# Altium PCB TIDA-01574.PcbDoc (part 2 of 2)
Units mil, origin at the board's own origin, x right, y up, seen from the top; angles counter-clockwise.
Board outline 4950 x 3450 mil, 2 copper layers (Top Layer, Bottom Layer), stack 62 mil thick; 82 components, 33 nets, 179 pads, 119 vias.
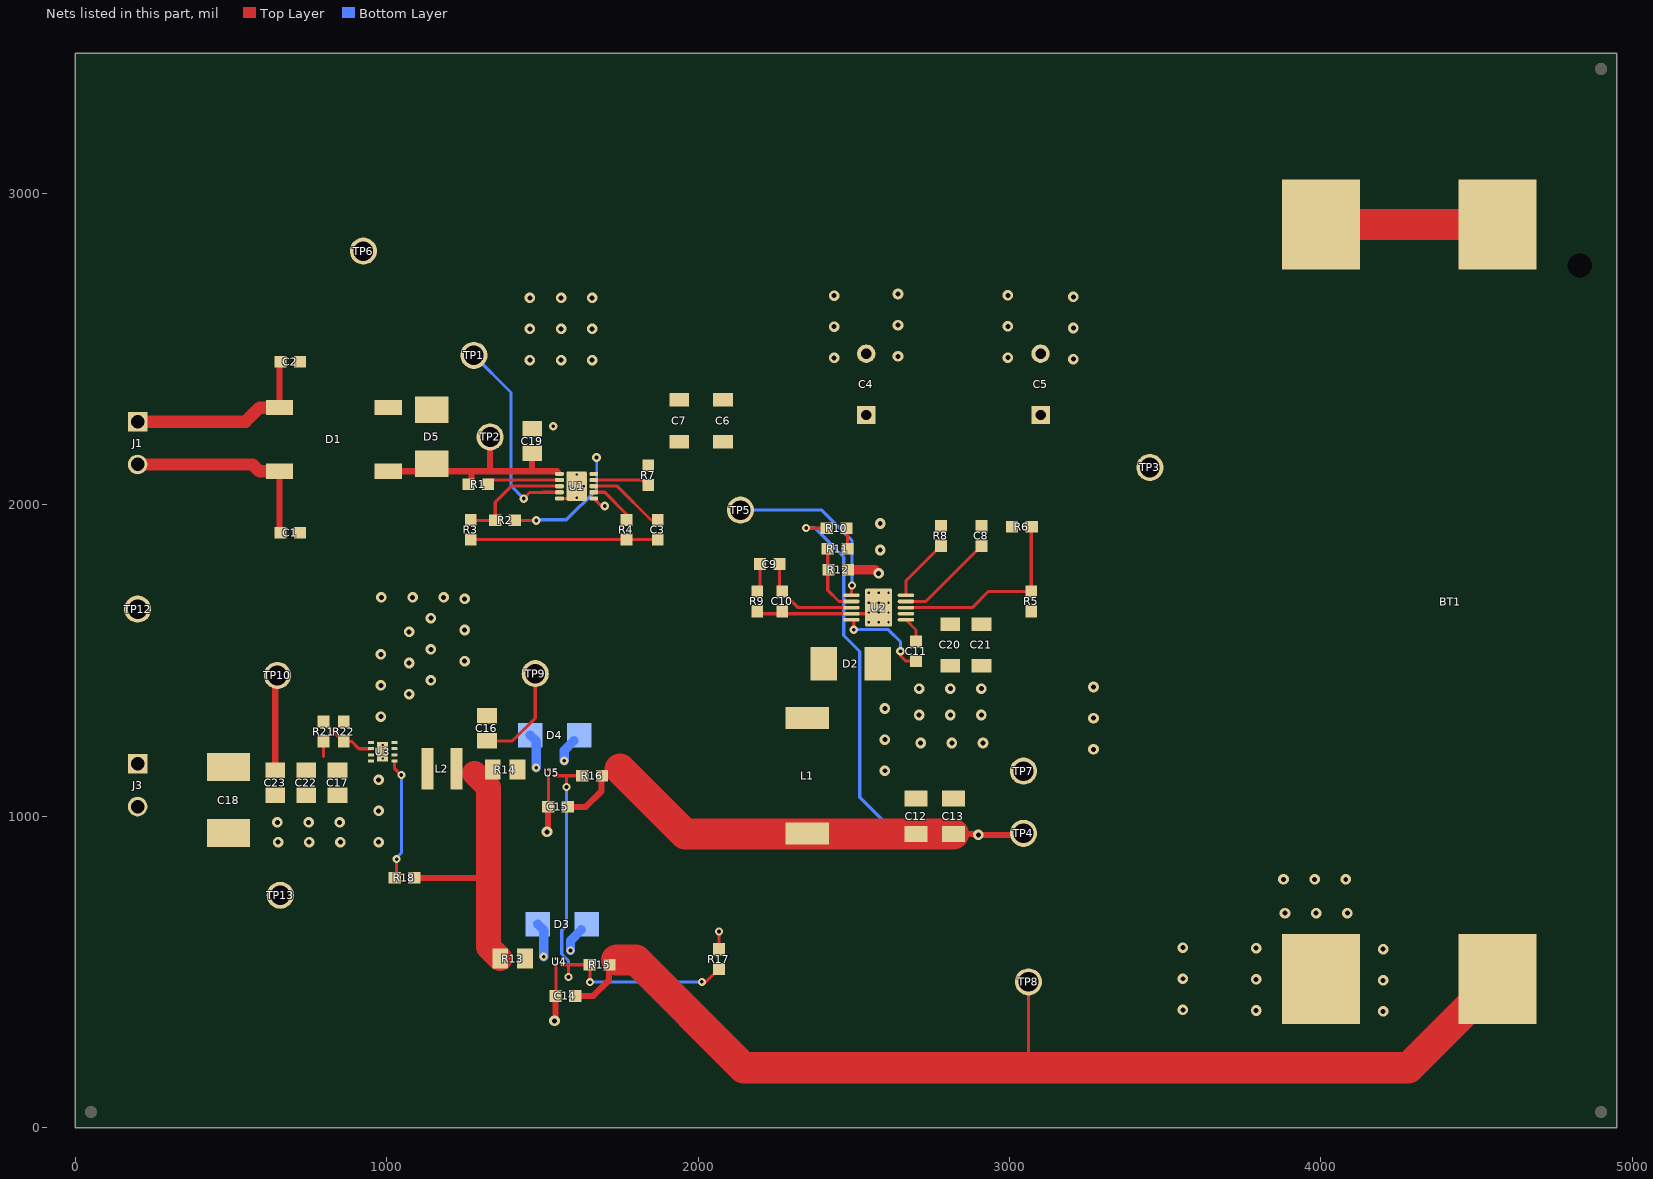
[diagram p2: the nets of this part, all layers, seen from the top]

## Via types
v1: diameter 34, hole 16, Top Layer to Bottom Layer, 81 vias
v2: diameter 26, hole 12, Top Layer to Bottom Layer, 13 vias
v3: diameter 19.68, hole 7.87, Top Layer to Bottom Layer, 12 vias
v4: diameter 28, hole 12, Top Layer to Bottom Layer, 7 vias
v5: diameter 19.68, hole 7.87, Top Layer to Bottom Layer, tented both sides, 6 vias

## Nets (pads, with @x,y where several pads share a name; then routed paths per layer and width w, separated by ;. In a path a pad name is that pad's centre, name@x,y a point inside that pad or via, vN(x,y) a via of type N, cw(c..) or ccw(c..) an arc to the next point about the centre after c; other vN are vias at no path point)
3p3V: C12.1 C13.1 C15.1 D4.2 L1.2 R10.2 R16.1 TP4.1 U5.A2 | length 3111.6
  Top Layer w10: 1958.09,942.91 1971.76,929.24 ; v2(2347,1926) 2348,1925 R10.2@2413.5,1925
  Top Layer w20: C15.1@1581.34,1029.84 1639.84,1029.84 1689.84,1079.84 R16.1@1689.84,1129.84 ; C13.1@2820,942.91 2897.09,942.91 v1(2900,940) 3040,940 TP4.1@3045,945
  Top Layer w100: 1749,1152 1958.09,942.91 C12.1@2700,942.91 C13.1@2820,942.91
  Bottom Layer w10: v2(2347,1926) 2374.27,1926 2467.65,1832.62 2467.65,1580.35 2519,1529 2519,1061 2640,940 v1(2900,940)
  Bottom Layer w30: v2(1570,1178) 1570,1211.26 D4.2@1600.87,1242.13
GND: BT1.3 C1.2 C2.2 C4.2 C5.2 C6.2 C7.2 C8.2 C10.2 C12.2 C13.2 C14.2 C15.2 C16.2 C17.2 C18.2 C19.2 C20.2 C21.2 C22.2 C23.2 D1.2 D2.2 D5.2 J3.2 R6.1 R8.1 R9.1 R12.1 R17.1 R22.1 TP6.1 TP7.1 TP12.1 TP13.1 U1.6 U2.9 U2.11@2580,1670 U3.1 U3.9@987,1207 U4.B1 U5.B1 | length 937.9
  Top Layer w10: C15.2@1518.35,1029.84 1520,1031.5 U5.B1@1520,1130 ; C14.2@1542.35,422.84 1544,424.5 U4.B1@1544,523 ; U1.6@1665.12,2020.63 v4@1689.75,1996 ; R17.1@2067,572.5 R17.1@2067,575.5 ; v2(2067,630) R17.1@2067,575.5 ; R17.1@2070,572.5 R17.1@2067,575.5 ; R9.1@2190,1658.5 2198.19,1650.31 U2.9@2492.4,1650.31 U2.11@2560.31,1650.31
  Top Layer w20: v1(1514.84,949.84) 1518.35,953.35 C15.2@1518.35,1029.84 ; v1(1538.84,342.84) 1542.35,346.35 C14.2@1542.35,422.84
  Top Layer w30: R12.1@2481.5,1791 2569,1791 v1(2580,1780)
  other v1: 4200,373 3792,376 3557,378 4200,473 3792,476 3557,478 4200,573 3792,576 3557,578 3885,689 3985,689 4085,689 3880,797 3980,797 4080,797 651,917 751,917 851,917 974,917 649,980 749,980 849,980 974,1017 974,1117 2600,1146 3270,1215 2715,1235 2815,1235 2915,1235 2600,1246 3270,1315 981,1320 2710,1325 2810,1325 2910,1325 2600,1346 1072,1392 2710,1410 2810,1410 2910,1410 3270,1415 981,1420 1142,1436 1072,1492 1250,1498 981,1520 1142,1536 1072,1592 1250,1598 1142,1636 1250,1698 983,1703 1083,1703 1183,1703 2585,1855 2585,1940 1460,2465 1560,2465 1660,2465 3205,2468 2437,2472 2995,2473 2642,2477 1460,2565 1560,2565 1660,2565 3205,2568 2437,2572 2995,2573 2642,2577 1460,2665 1560,2665 1660,2665 3205,2668 2437,2672 2995,2673 2642,2677
  other v3: 987,1185.35 987,1228.65 2548.5,1654.25 2580,1654.25 2611.5,1654.25 2548.5,1685.75 2580,1685.75 2611.5,1685.75
  other v4: 1700,1996 1535,2252
  other v5: 2548.5,1622.76 2580,1622.76 2611.5,1622.76 2548.5,1717.24 2580,1717.24 2611.5,1717.24
NetBT1_1: BT1.1 C14.1 D3.2 R15.1 TP8.1 U4.A2 | length 3597.5
  Top Layer w10: 3061,221 TP8.1@3061,468
  Top Layer w20: C14.1@1605.34,422.84 1663.84,422.84 1713.84,472.84 R15.1@1713.84,522.84
  Top Layer w100: 1738.82,537.84 1800.16,537.84 2146,192 4281.88,192 BT1.1@4567.86,477.98
  Bottom Layer w30: v2(1590,569) 1590,600.26 1594,604.26 D3.2@1624.87,635.13
NetBT1_2: BT1.2 BT1.4 | length 567.7
  Top Layer w100: BT1.4@4000.14,2900.02 BT1.2@4567.86,2900.02
NetC1_1: C1.1 D1.4 J1.2 | length 659.2
  Top Layer w20: C1.1@655.5,1913 D1.4@655.5,2107.64
  Top Layer w40: J1.2@200,2129.6 569.54,2129.6 591.5,2107.64 D1.4@655.5,2107.64
NetC2_1: C2.1 D1.3 J1.1 | length 618.8
  Top Layer w20: D1.3@655.5,2312.36 C2.1@655.5,2457
  Top Layer w40: J1.1@200,2267.39 546.53,2267.39 591.5,2312.36 D1.3@655.5,2312.36
NetC3_1: C3.1 U1.8 | length 249.8
  Top Layer w10: U1.8@1665.12,2060 1740,2060 1848.5,1951.5 C3.1@1870,1951.5
NetC3_2: C3.2 R3.1 R4.1 U1.5 U1.11@1610,2060 | length 683.1
  Top Layer w10: R3.1@1270,1888.5 R4.1@1770,1888.5 C3.2@1870,1888.5 ; U1.5@1554.88,2020.63 1590.63,2020.63 1610,2040 U1.11@1610,2060
  other v3: 1610,2022.6 1587.36,2060 1632.64,2060 1610,2097.4
NetC4_1: C4.1 C5.1 C6.1 C7.1 C20.1 C21.1 R2.2 R5.2 R7.2 TP3.1 U1.10 U2.2 | length 406.5
  Top Layer w10: R2.2@1411.5,1950 v4(1480,1950)
  Bottom Layer w8: 1674,2049 v4(1674,2152)
  Bottom Layer w10: v4(1480,1950) 1482,1952 1577,1952 1674,2049
NetC8_1: C8.1 U2.4 | length 316.5
  Top Layer w10: U2.4@2667.6,1689.68 2731.18,1689.68 C8.1@2910,1868.5
NetC9_1: C9.1 C10.1 U2.8 | length 335.8
  Top Layer w10: C9.1@2261.5,1810 2261.5,1730 C10.1@2270,1721.5 2321.5,1670 U2.8@2492.4,1670
NetC9_2: C9.2 R9.2 | length 80
  Top Layer w10: R9.2@2198.5,1730 C9.2@2198.5,1810
NetC11_1: C11.1 D2.1 L1.1 U2.10 | length 291.9
  Top Layer w10: v4(2500,1599.13) 2500,1623.03 ; v4(2650,1530) 2650,1515 2666.5,1498.5 C11.1@2700,1498.5
  Bottom Layer w10: v4(2500,1599.13) 2610.87,1599.13 2650,1560 v4(2650,1530)
NetC11_2: C11.2 U2.1 | length 82.6
  Top Layer w10: U2.1@2667.6,1630.63 2700,1598.23 C11.2@2700,1561.5
NetC16_1: C16.1 L2.1 R13.2 R14.2 R18.1 TP9.1 U3.8 | length 1195.7
  Top Layer w10: C16.1@1322,1242 1404,1242 1477,1315 TP9.1@1477,1458
  Top Layer w20: R18.1@1088.5,802 1327,802
  Top Layer w80: 1282,1138 1327,1093 1327,802 1327,580 R13.2@1364,543
NetC17_1: C17.1 C18.1 C22.1 C23.1 J3.1 R21.2 TP10.1 U3.3 U3.4 | length 356.4
  Top Layer w10: 797,1192 R21.2@797,1240.5
  Top Layer w20: C23.1@642,1147 642,1445 TP10.1@649,1452
NetC19_1: C19.1 D1.1 D5.1 R1.2 TP2.1 U1.1 | length 742.4
  Top Layer w20: D1.1@1004.5,2107.64 1272,2107.64 ; R1.2@1272,2075.5 1272,2107.64 ; 1332,2110.64 TP2.1@1332,2218 ; 1467,2108.64 C19.1@1467,2165 ; U1.1@1549.96,2105 1547.32,2107.64 1272,2107.64
NetD3_1: D3.1 R13.1 U4.A1 | length 112.2
  Top Layer w10: R13.1@1444,543 R13.1@1444.31,542.68
  Bottom Layer w30: D3.1@1485.26,653 1504,634.26 v2(1504,549)
NetD4_1: D4.1 R14.1 U5.A1 | length 112.2
  Top Layer w10: R14.1@1420,1150 R14.1@1420.31,1149.68
  Bottom Layer w30: D4.1@1461.26,1260 1480,1241.26 v2(1480,1156)
NetL2_2: L2.2 U3.6 U3.7
NetR1_1: R1.1 U1.2 | length 235.2
  Top Layer w10: R1.1@1319.69,2079.69 U1.2@1554.88,2079.69
NetR2_1: R2.1 R3.2 U1.3 | length 363.2
  Top Layer w10: R3.2@1271.5,1950 R2.1@1348.5,1950 1348.5,2008.5 1400,2060 U1.3@1554.88,2060
NetR4_2: R4.2 U1.7 | length 134
  Top Layer w10: U1.7@1665.12,2040.31 1699.69,2040.31 R4.2@1770,1970
NetR5_1: R5.1 R6.2 U2.3 | length 630.7
  Top Layer w10: U2.3@2667.6,1670 2880,1670 2931.5,1721.5 R5.1@3070,1721.5 R6.2@3070,1928.5
NetR7_1: R7.1 U1.9 | length 181.5
  Top Layer w10: U1.9@1665.12,2079.68 1818.82,2079.68 R7.1@1838.5,2060
NetR8_2: R8.2 U2.5 | length 205.7
  Top Layer w10: U2.5@2667.6,1709.37 2667.6,1756.1 R8.2@2780,1868.5
NetR10_1: R10.1 R11.2 | length 67.2
  Top Layer w10: R10.1@2476.5,1925 2479.5,1922 R11.2@2479.5,1859
NetR11_1: R11.1 R12.2 U2.7 | length 224.2
  Top Layer w10: R11.1@2416.5,1859 2416.5,1725.5 2452.32,1689.68 U2.7@2492.4,1689.68
NetR15_2: R15.2 R16.2 R17.2 U4.B2 U5.B2 | length 1359.4
  Top Layer w10: U5.B2@1539.68,1130 1579.68,1130 1579.84,1129.84 R16.2@1628.35,1129.84 ; U4.B2@1563.68,523 1603.68,523 1603.84,522.84 R15.2@1652.35,522.84 1652.35,473.35 1653,472.69 v2(1653,467) ; v2(1577,1094) 1577,1127 ; v2(1584,484) 1584,520 ; v2(2012,468) 2025.5,468 R17.2@2067,509.5
  Bottom Layer w10: v2(1577,1094) 1577,648.55 1562.13,633.68 1562.13,557.45 1584,535.58 v2(1584,484) ; v2(1653,467) 2011,467 v2(2012,468)
NetR18_2: R18.2 U3.5 | length 393.7
  Top Layer w10: U3.5@1024.4,1177.47 1024.4,1154.6 v2(1047,1132) ; R18.2@1025.5,802 1027,803.5 1032,808.5 v2(1032,862)
  Bottom Layer w10: v2(1032,862) 1032,867 1047,882 v2(1047,1132)
NetR21_1: R21.1 R22.2 U3.2 | length 188.5
  Top Layer w10: R21.1@797,1303.5 859.99,1240.5 R22.2@862,1240.5 886.76,1240.5 910.42,1216.84 U3.2@949.6,1216.84
NetTP1_1: TP1.1 U1.4 | length 649.6
  Top Layer w10: v4(1440,2020) 1460,2040 1500,2040 1500.32,2040.32 U1.4@1554.88,2040.32
  Bottom Layer w10: TP1.1@1280,2480 1399,2361 1399,2061 v4(1440,2020)
NetTP5_1: TP5.1 U2.6 | length 576.1
  Top Layer w10: U2.6@2492.4,1709.37 2492.4,1740.4 2493,1741 v2(2494,1741)
  Bottom Layer w10: TP5.1@2136,1983 2397,1983 2494,1886 v2(2494,1741)
pads on no net: BT1.MH1 FID1.1 FID2.1 FID3.1 H1.0 H2.0 H3.0 H4.0 U1.11@1600.16,1999.76 U1.11@1600.16,2120.24 U1.11@1610,2035.2 U1.11@1610,2084.8 U1.11@1619.84,1999.76 U1.11@1619.84,2120.24 U2.11@2580,1670 U3.9@987,1189.28 U3.9@987,1224.72

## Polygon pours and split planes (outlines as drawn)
GND on Top Layer "TOP_LAYER_GND_P000" (solid, remove dead copper, pour order 0): 700,1880 700,3450 4950,3450 4950,2440 2340,2440 2200,2300 1815,2300 1550,2300 1550,2220 1370.26,2220 1370.26,2280 950,2280 950,1880
GND on Bottom Layer "BOTTOM_LAYER_GND_P002" (solid, remove dead copper, pour order 2): 0,0 4950,0 4950,3450 0,3450

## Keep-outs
Keep-Out Layer:
  text ".Layer_Name" at 577,-858.49 h60

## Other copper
Top Layer:
  rectangle net NetC19_1: 1535,2095 1565,2120
  rectangle net NetC3_2: 1576.15,1855 1645,2275
  rectangle net GND: 2535,1395 2625,1975
  rectangle net GND: 2535,1900 3030,1975
  region net 3p3V: 1535,1145 1597,1145 1597,1157 1666,1157 1666,1111 1772,1111 1772,1194 1535,1194
  region net NetD3_1: 1550,538 1540,538 1510,508 1419,508 1419,575 1550,575
  region net NetBT1_1: 1559,538 1621,538 1621,550 1690,550 1690,504 1796,504 1796,587 1559,587
  region net NetD4_1: 1526,1145 1516,1145 1486,1115 1395,1115 1395,1182 1526,1182
  region net GND: 902,1098 128,1098 128,870 1005,870 1005,1287 1367,1287 1367,1799 844,1799 844,1285 888.3,1285 942.3,1231 969,1231 969,1165
  region net NetC16_1: 1017,1232 1197,1232 1197,1077 1367,1077 1367,1267 1017,1267
  region net NetL2_2: 1017,1222 1157,1222 1157,1077 1107,1077 1077.92,1106.08 1077.92,1161.08 1047,1192 1017,1192
  region net NetC17_1: 960,1202 128,1202 128,1122 911,1122 960,1171
  region net NetC4_1: 1655,2095 2200,2095 2300,1995 3570,1995 3570,2325 2300,2325 2200,2225 1655,2225
  region net NetC4_1: 2670,1655 2935,1655 2960,1680 3050,1680 3160,1680 3180,1700 3180,2000 3165,2015 3165,2325 3330,2325 3330,2005 3330,1550 2800,1550 2704.26,1645.74 2675.54,1645.74
  region net GND: 2535,1510 2630,1510 2630,1465 2740,1465 2780,1505 4252,1505 4252,1025 4252,305 3385,305 3385,1025 2535,1025
  region net NetC11_1: 2515,1635 2445,1635 2355,1550 2355,1435 2270,1350 2270,1275 2450,1275 2450,1520 2475,1545 2515,1585
  text ".Layer_Name" at 577,-858.49 h60
Bottom Layer:
  text ".Layer_Name" at 577,-858.49 h60

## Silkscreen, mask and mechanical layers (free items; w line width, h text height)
Top Overlay:
  region: 2646,196 2346,196 2346,96 2646,96
  text "'.PRJ_Number'.PCB_Rev-" at 1595,114 h108.27
  text ".Layer_Name" at 577,-858.49 h60
Bottom Overlay:
  text ".Layer_Name" at 577,-858.49 h60
Top Paste:
  text ".Layer_Name" at 577,-858.49 h60
Bottom Paste:
  text ".Layer_Name" at 577,-858.49 h60
Top Solder:
  text ".Layer_Name" at 577,-858.49 h60
  text ".Layer_Name" at 577,-858.49 h60
Bottom Solder:
  text ".Layer_Name" at 577,-858.49 h60
Drill Guide:
  text ".Layer_Name" at 577,-858.49 h60
M1 Board Outline:
  the board outline again, w10
  text ".Layer_Name" at 577,-858.49 h60
M2 Board Dimensions:
  rectangle: 0,-275 125,-150
  rectangle: 125,-400 500,-275
  lines w7: 0,-275 1000,-275 ; 125,-400 125,-150 ; 250,-400 250,-150 ; 500,-400 500,-150 ; 750,-400 750,-150 ; 0,-400 1000,-400 1000,-150 0,-150 0,-400
  text ".Layer_Name" at 577,-858.49 h60
M3 3D STEP Top:
  text ".Layer_Name" at 577,-858.49 h60
M4 3D STEP Bottom:
  text ".Layer_Name" at 577,-858.49 h60
M5 Assembly Top:
  lines w10: -292,-930.17 6308,-930.17 ; -292,-726.83 6310,-726.83 ; -292,-523.5 -292,-1133.5 3713,-1133.5 6310,-1133.5 6310,-523.5 -291.5,-523.5 -291.5,-1133.5 1284,-1133.5 ; 2173,-1133.5 2173,-523.5 ; 3440,-726.83 3440,-523.5 ; 4280,-726.83 4280,-523.5 ; 4902,-1140 4902,-937.17
  text "COMPONENTS MARKED 'DNP' SHOULD NOT BE POPULATED." at 1153.5,-318.5 h60
  text "ASSEMBLY VARIANT:" at 1153,-434 h60
  text ".VariantName" at 2189,-434 h60
  text "PCB VIEWED FROM TOP SIDE" at -228.5,-655.67 h60
  text "BOARD #:" at 2248,-655.67 h60
  text ".PRJ_Number" at 2793.5,-655.67 h60
  text "REV:" at 3638,-655.67 h60
  text ".PCB_Rev" at 3929.5,-655.67 h60
  text "SVN REV:" at 4476,-655.67 h60
  text ".VersionControl_RevNumber" at 4982,-655.67 h60
  text "TID #:" at 2248,-859 h60
  text ".TID" at 2793.5,-859 h60
  text "PLOT NAME =" at -228.5,-1064.34 h60
  text ".plot_File_Name" at 577,-1064.34 h60
  text "GENERATED    :" at 2250,-1064.34 h60
  text ".Print_Date" at 3119.5,-1064.34 h60
  text ".Print_Time" at 3848.5,-1064.34 h60
  text "TEXAS INSTRUMENTS" at 5113,-1064.34 h60
M6 Assembly Bottom:
  lines w10: -292.5,-727.33 6309.5,-727.33 ; -290.5,-930.67 6309.5,-930.67 ; 1115.5,-1140.5 1115.5,-937.67 ; 1737.5,-727.33 1737.5,-524 ; 2577.5,-727.33 2577.5,-524 ; 3844.5,-1134 3844.5,-524 ; 4733.5,-1134 6309,-1134 6309,-524 -292.5,-524 -292.5,-1134 2304.5,-1134 6309.5,-1134 6309.5,-524
  text "COMPONENTS MARKED 'DNP' SHOULD NOT BE POPULATED." at 6102,-318 h60
  text ".VariantName" at 5058,-434 h60
  text "ASSEMBLY VARIANT:" at 6097,-434 h60
  text ".VersionControl_RevNumber" at 1035.5,-656.17 h60
  text "SVN REV:" at 1541.5,-656.17 h60
  text ".PCB_Rev" at 2088,-656.17 h60
  text "REV:" at 2379.5,-656.17 h60
  text ".PRJ_Number" at 3224,-656.17 h60
  text "BOARD #:" at 3769.5,-656.17 h60
  text "PCB VIEWED FROM BOTTOM SIDE" at 6246,-656.17 h60
  text ".TID" at 3224,-859.5 h60
  text "TID #:" at 3769.5,-859.5 h60
  text "TEXAS INSTRUMENTS" at 904.5,-1064.84 h60
  text ".Print_Time" at 2169,-1064.84 h60
  text ".Print_Date" at 2898,-1064.84 h60
  text "GENERATED    :" at 3767.5,-1064.84 h60
  text ".plot_File_Name" at 5440.5,-1064.84 h60
  text "PLOT NAME =" at 6246,-1064.84 h60
M9 Title Sheet:
  drawing of 57 lines, arcs and shapes, not listed
  text "1" at 739.84,8036.5 h70
  text "2" at 3235.5,8036.5 h70
  text "3" at 5724.84,8036.5 h70
  text "4" at 8231.51,8036.5 h70
  text "5" at 10730.5,8036.5 h70
  text "6" at 13235.5,8036.5 h70
  text "A" at -416.5,6893.5 h70
  text "A" at 14383.5,6893.5 h70
  text "B" at -416.5,4513.5 h70
  text "B" at 14383.5,4513.5 h70
  text "C" at -416.5,2138.5 h70
  text "C" at 14383.5,2138.5 h70
  text "PROJECT TITLE:" at 11343.5,277.5 h45
  text ".PRJ_Title" at 11393.5,144.17 h70
  text "DESIGNED FOR:" at 11343.5,-23.5 h45
  text ".PRJ_Customer" at 11393.5,-163.5 h70
  text "D" at -416.5,-231.5 h70
  text "D" at 14383.5,-231.5 h70
  text "FILE NAME:" at 11343.5,-323.5 h45
  text ".PCB_File_Name_No_Path" at 11393.5,-443.5 h70
  text "Texas Instruments (TI) and/or its licensors do not warrant the accuracy or completeness of this specification" at 6374,-605.34 h45
  text "ENGINEER:" at 11343.5,-613.5 h45
  text "LAYOUT BY:" at 12848.5,-613.5 h45
  text "or any information contained therein. TI and/or its licensors do not warrant that this design will meet" at 6329.01,-718 h45
  text ".PRJ_Engineer" at 11393.5,-768.49 h70
  text ".PCB_Layout" at 12899,-768.49 h70
  text "the specifications, will be suitable for your application or fit for any particular purpose, or will operate in" at 6329.01,-830.67 h45
  text ".Layer_Name" at 577,-858.49 h60
  text "ALTIUM DESIGNER VERSION:" at 12848.5,-923.5 h45
  text "an implementation. TI and/or its licensors do not warrant that the design is production worthy. You should" at 6329.01,-943.33 h45
  text "completely validate and test your design implementation to confirm the system functionality for your application." at 6374,-1056 h45
  text ".print_Scale" at 11393.5,-1056.83 h70
  text ".Application_BuildNumber" at 12899,-1056.83 h70
  text "1" at 739.84,-1263.5 h70
  text "2" at 3235.5,-1263.5 h70
  text "3" at 5724.84,-1263.5 h70
  text "4" at 8231.51,-1263.5 h70
  text "5" at 10730.5,-1263.5 h70
  text "6" at 13235.5,-1263.5 h70
M10 Fab Notes:
  drawing of 189 lines, arcs and shapes, not listed
  text "DESIGN INFORMATION" at 12382.02,6356.17 h60
  text "MIN. TRACK WIDTH:" at 11737.46,6224.05 h60
  text "8" at 12833.7,6224.05 h60
  text "MIL" at 12988.46,6224.05 h60
  text "MIN. CLEARANCE:" at 11737.46,6099.92 h60
  text "0.2" at 12773.7,6099.93 h60
  text "mm" at 12988.46,6099.92 h60
  text "MIN. VIA PAD SIZE:" at 11737.46,5975.8 h60
  text "24" at 12803.71,5975.8 h60
  text "MIL" at 12988.46,5975.8 h60
  text "0.05mm (2MIL)" at 12432.46,5845.9 h60
  text "MINIMUM ANNULAR RING" at 11408.23,5837.67 h60
  text "EXTERNAL" at 13140.46,5837.67 h60
  text "PER" at 11608.23,5727.55 h60
  text "IPC-D-275 CLASS 2 LEVEL C" at 11828.23,5727.54 h60
  text "MIL, HOLES" at 13316.46,5627.07 h60
  text "+/-" at 12924,5618.48 h60
  text "+/-" at 13778,5618.48 h60
  text "REGISTRATION TOLERANCES:" at 11408.23,5617.42 h60
  text "METAL" at 12608,5617.42 h60
  text "5" at 13184.2,5617.42 h60
  text "3" at 14017.2,5617.42 h60
  text "MIL" at 14133.46,5617.42 h60
  text "HOLE SIZE TOLERANCE (UNLESS OTHERWISE SPECIFIED):" at 11408.23,5519.1 h60
  text "+/-" at 13778,5516.23 h60
  text "3" at 14017.2,5515.17 h60
  text "MIL" at 14133.46,5515.17 h60
  text "MATERIAL:" at 11333.46,5377.52 h60
  text "FR-4 High Tg" at 12319.9,5249 h60
  text "X" at 12175.46,5241.01 h60
  text "FR-408" at 11754.46,5236.49 h60
  text "OTHER" at 13242.46,5236.49 h60
  text "62 MIL (1.6mm) +/-10%" at 12074.56,5093.46 h60
  text "X" at 11954.46,5091.01 h60
  text "THICKNESS:" at 11408.23,5085.24 h60
  text "OTHER" at 13359.46,5085.24 h60
  text "TOLERANCE:" at 11408.23,4946.92 h60
  text "X" at 12256.46,4946.92 h60
  text "ANSI IPC-6012 TYPE 3 CLASS 2" at 12434.48,4946.92 h60
  text "OTHER +/-" at 12434.46,4802.73 h60
  text "BOW & TWIST:" at 11408.23,4657.54 h60
  text "X" at 12256.46,4657.54 h60
  text "ANSI IPC-6012 TYPE 3 CLASS 2" at 12434.48,4657.54 h60
  text "OTHER +/-" at 12434.46,4510.85 h60
  text "DRILLING:" at 11333.46,4380.23 h60
  text "NC_DRILL FILES" at 13094.46,4275.04 h60
  text "REFERENCE:" at 11408.23,4271.1 h60
  text "X" at 12065.46,4271.01 h60
  text "AS SHOWN" at 12243.46,4271.1 h60
  text "X" at 12966.46,4271.1 h60
  text "OTHER" at 13392.46,4128.85 h60
  text "PTH COPPER THICKNESS:" at 11407.91,4125.32 h60
  text "X" at 12547.14,4125.32 h60
  text "20-30 um" at 12675.14,4125.32 h60
  text "BOARD FINISH:" at 11333.46,3977.73 h60
  text "SILKSCREEN:" at 11488.68,3867.6 h60
  text "X" at 12446.46,3867.6 h60
  text "TOP" at 12563.46,3867.6 h60
  text "X" at 12956.46,3867.6 h60
  text "BOTTOM" at 13074.46,3867.6 h60
  text "SILKSCREEN COLOR:" at 11488.68,3712.41 h60
  text "X" at 12445.46,3712.41 h60
  text "WHITE" at 12563.46,3712.41 h60
  text "OTHER" at 13074.46,3712.41 h60
  text "X" at 12576.46,3568.96 h60
  text "GREEN" at 12694.46,3568.96 h60
  text "OTHER" at 13312.46,3568.96 h60
  text "SOLDER RESIST COLOR:" at 11488.68,3562.1 h60
  text "X" at 12576.46,3414.71 h60
  text "MATTE" at 12694.46,3414.71 h60
  text "SEMI-GLOSS" at 13312,3414.07 h60
  text "IMMERSION GOLD (ENIG)" at 12394.46,3241.94 h60
  text "ENEPIG" at 13732,3234.72 h60
  text "SURFACE FINISH:" at 11333.46,3233.72 h60
  text "X" at 12216.46,3233.72 h60
  text "IMM. TIN/SILVER OR EQUIV" at 11663,3096.4 h60
  text "OTHER" at 13094.46,3092.47 h60
  text "ARRAY/PANEL:" at 11333.46,2937.09 h60
  text "CUT AND TRIM PER M1 BOARD OUTLINE" at 12394.46,2928.87 h60
  text "N.C. ROUTE" at 12394.46,2792.9 h60
  text "X" at 13082.46,2792.9 h60
  text "V. SCORE" at 13260.46,2792.9 h60
  text "CERTIFICATION:" at 11333.46,2663.77 h60
  text "MATERIALS AND WORKMANSHIP FOR ALL PCBS" at 12058.46,2663.77 h60
  text "TO MEET OR EXCEED THE REQUIREMENTS OF:" at 12058.46,2569.71 h60
  text "X" at 11695.97,2441.08 h60
  text "ANSI IPC-A-600F CLASS ->" at 11823.96,2441.08 h60
  text "X" at 13471.97,2441.08 h60
  text "2" at 13581.96,2441.08 h60
  text "1" at 13266.96,2439.58 h60
  text "3" at 13935.96,2439.58 h60
  text "X" at 12507.97,2293.39 h60
  text "RoHS" at 12635.96,2293.39 h60
  text "OTHER" at 13280.36,2293.39 h60
  text "PER ORDER" at 13677.42,2293.39 h60
  text "ALL BOARDS MUST MEET OR EXCEED UL94-V0 REQUIREMENTS." at 11361,2139.57 h60
  text "PCB MUST BEAR THE UL94V-0 UL REGISTERED MATERIAL ID NUMBER" at 11361,2023.5 h60
  text "ADDITIONAL REQUIREMENTS:" at 11333.46,1854.08 h60
  text "MICROSECTION:" at 11408.23,1746.95 h60
  text "YES" at 12313.96,1746.95 h60
  text "REQUIRED" at 13175.46,1602.62 h60
  text "BARE BOARD ELEC. TEST:" at 11408.23,1599.76 h60
  text "NONE" at 12713.96,1599.76 h60
  text "X" at 13057.46,1599.76 h60
  text "PER ORDER" at 13767.46,1599.76 h60
  text "XX MIL VIAS REQUIRE NON-CONDUCTIVE FILL AND PLANARIZE" at 11576.38,1394.82 h59
  text "XX MIL VIAS REQUIRE CONDUCTIVE FILL AND PLANARIZE" at 11584.38,1290.84 h60
  text "OUTER XX MIL TRACES REQUIRE 50 OHM SINGLE-ENDED IMPEDANCE" at 11583.39,1127.46 h58
  text "LAYER 2 & 3 (INNER LAYERS) XX MIL WIDE, XX MIL SPACE / TRACES REQUIRE 100 OHM DIFFERENTIAL IMPEDANCE" at 11575.39,891.74 h60
  text ".Layer_Name" at 577,-858.49 h60
M11 Gerber Information:
  lines w10: -292,-930.17 6308,-930.17 ; -292,-726.83 6310,-726.83 ; -292,-523.5 -292,-1133.5 3713,-1133.5 6310,-1133.5 6310,-523.5 -291.5,-523.5 -291.5,-1133.5 1284,-1133.5 ; 2173,-1133.5 2173,-523.5 ; 3440,-726.83 3440,-523.5 ; 4280,-726.83 4280,-523.5 ; 4902,-1140 4902,-937.17
  text "ALL ARTWORK VIEWED FROM TOP SIDE" at -228.5,-655.67 h60
  text "BOARD #:" at 2248,-655.67 h60
  text ".PRJ_Number" at 2793.5,-655.67 h60
  text "REV:" at 3638,-655.67 h60
  text ".PCB_Rev" at 3929.5,-655.67 h60
  text "SVN REV:" at 4476,-655.67 h60
  text ".VersionControl_RevNumber" at 4982,-655.67 h60
  text "LAYER NAME =" at -228.5,-858.49 h60
  text "TID #:" at 2248,-859 h60
  text ".TID" at 2793.5,-859 h60
  text "PLOT NAME =" at -228.5,-1064.34 h60
  text ".plot_File_Name" at 577,-1064.34 h60
  text "GENERATED    :" at 2250,-1064.34 h60
  text ".Print_Date" at 3119.5,-1064.34 h60
  text ".Print_Time" at 3848.5,-1064.34 h60
  text "TEXAS INSTRUMENTS" at 5113,-1064.34 h60
M12 Stackup:
  drawing of 191 lines, arcs and shapes, not listed
  text "Layer" at 9797.84,7830 h60
  text "Name" at 10207.76,7830 h60
  text "Material" at 11137.5,7830 h60
  text "Thickness" at 11997.27,7830 h60
  text "Constant" at 12647.1,7830 h60
  text "Board Layer Stack" at 13216.96,7830 h60
  text "1" at 9797.84,7710 h60
  text "Top Overlay" at 10207.76,7710 h60
  text "2" at 9797.84,7590 h60
  text "Top Solder" at 10207.76,7590 h60
  text "Solder Resist" at 11137.5,7590 h60
  text "0.40mil" at 11997.27,7590 h60
  text "3.5" at 12647.1,7590 h60
  text "3" at 9797.84,7470 h60
  text "Top Layer" at 10207.76,7470 h60
  text "Copper" at 11137.5,7470 h60
  text "1.40mil" at 11997.27,7470 h60
  text "4" at 9797.84,7350 h60
  text "Dielectric1" at 10207.76,7350 h60
  text "FR-4" at 11137.5,7350 h60
  text "59.20mil" at 11997.27,7350 h60
  text "4.8" at 12647.1,7350 h60
  text "5" at 9797.84,7230 h60
  text "Bottom Layer" at 10207.76,7230 h60
  text "Copper" at 11137.5,7230 h60
  text "1.40mil" at 11997.27,7230 h60
  text "6" at 9797.84,7110 h60
  text "Bottom Solder" at 10207.76,7110 h60
  text "Solder Resist" at 11137.5,7110 h60
  text "0.40mil" at 11997.27,7110 h60
  text "3.5" at 12647.1,7110 h60
  text "7" at 9797.84,6990 h60
  text "Bottom Overlay" at 10207.76,6990 h60
  text ".Layer_Name" at 577,-858.49 h60
M13 Component Bodies Top:
  text ".Layer_Name" at 577,-858.49 h60
M14 Component Bodies Bottom:
  text ".Layer_Name" at 577,-858.49 h60
M15 Courtyards Top:
  text ".Layer_Name" at 577,-858.49 h60
M16 Courtyards Bottom:
  text ".Layer_Name" at 577,-858.49 h60
Drill Drawing:
  lines w10: 5326.76,2682.91 5371.04,2682.91 5371.04,2727.18 5326.76,2727.18 5326.76,2682.91 ; 5326.76,2826.81 5371.04,2826.81 5348.9,2782.53 5326.76,2826.81 ; 5326.76,2893.22 5337.83,2893.22 5348.9,2882.15 5359.97,2893.22 5371.04,2893.22 5359.97,2904.29 5371.04,2915.36 5359.97,2915.36 5348.9,2926.43 5337.83,2915.36 5326.76,2915.36 5337.83,2904.29 5326.76,2893.22 ; 5326.76,3003.91 5348.9,2981.77 5371.04,3003.91 5348.9,3026.05 5326.76,3003.91 ; 5326.76,3081.4 5326.76,3092.47 5337.83,3103.54 5326.76,3114.6 5326.76,3125.67 5337.83,3125.67 5348.9,3114.6 5359.97,3125.67 5371.04,3125.67 5371.04,3114.6 5359.97,3103.54 5371.04,3092.47 5371.04,3081.4 5359.97,3081.4 5348.9,3092.47 5337.83,3081.4 5326.76,3081.4 ; 5326.76,3181.02 5348.9,3192.09 5371.04,3181.02 5359.97,3203.16 5371.04,3225.3 5348.9,3214.23 5326.76,3225.3 5337.83,3203.16 5326.76,3181.02 ; 5326.76,3291.71 5337.83,3291.71 5337.83,3280.64 5359.97,3280.64 5359.97,3291.71 5371.04,3291.71 5371.04,3313.85 5359.97,3313.85 5359.97,3324.92 5337.83,3324.92 5337.83,3313.85 5326.76,3313.85 5326.76,3291.71
  lines w12: 5286,2653.02 8398.94,2653.02 ; 5286,3350.38 8398.94,3350.38 ; 5601.63,2553.4 5601.63,3450 ; 5918.82,2553.4 5918.82,3450 ; 6540.56,2553.4 6540.56,3450 ; 6784.88,2553.4 6784.88,3450 ; 7145.22,2553.4 7145.22,3450 ; 7854.73,2553.4 7854.73,3450 ; 5286,2553.4 8398.94,2553.4 8398.94,3450 5286,3450 5286,2553.4
  text "Symbol" at 5345.77,3380.26 h72
  text "Quantity" at 5631.52,3380.26 h72
  text "Finished Hole Size" at 5948.7,3380.26 h72
  text "Plated" at 6570.45,3380.26 h72
  text "Hole Type" at 6814.77,3380.26 h72
  text "Drill Layer Pair" at 7175.11,3380.26 h72
  text "Hole Tolerance" at 7884.62,3380.26 h72
  text "1" at 5631.52,3280.64 h60
  text "77.95mil (1.980mm)" at 5948.7,3280.64 h60
  text "NPTH" at 6570.45,3280.64 h60
  text "Round" at 6814.77,3280.64 h60
  text "Top Layer - Bottom Layer" at 7175.11,3280.64 h60
  text "18" at 5631.52,3181.02 h60
  text "7.87mil (0.200mm)" at 5948.7,3181.02 h60
  text "PTH" at 6570.45,3181.02 h60
  text "Round" at 6814.77,3181.02 h60
  text "Top Layer - Bottom Layer" at 7175.11,3181.02 h60
  text "20" at 5631.52,3081.4 h60
  text "12.00mil (0.305mm)" at 5948.7,3081.4 h60
  text "PTH" at 6570.45,3081.4 h60
  text "Round" at 6814.77,3081.4 h60
  text "Top Layer - Bottom Layer" at 7175.11,3081.4 h60
  text "81" at 5631.52,2981.77 h60
  text "16.00mil (0.406mm)" at 5948.7,2981.77 h60
  text "PTH" at 6570.45,2981.77 h60
  text "Round" at 6814.77,2981.77 h60
  text "Top Layer - Bottom Layer" at 7175.11,2981.77 h60
  text "4" at 5631.52,2882.15 h60
  text "33.47mil (0.850mm)" at 5948.7,2882.15 h60
  text "PTH" at 6570.45,2882.15 h60
  text "Round" at 6814.77,2882.15 h60
  text "Top Layer - Bottom Layer" at 7175.11,2882.15 h60
  text "4" at 5631.52,2782.53 h60
  text "43.31mil (1.100mm)" at 5948.7,2782.53 h60
  text "PTH" at 6570.45,2782.53 h60
  text "Round" at 6814.77,2782.53 h60
  text "Top Layer - Bottom Layer" at 7175.11,2782.53 h60
  text "12" at 5631.52,2682.91 h60
  text "63.00mil (1.600mm)" at 5948.7,2682.91 h60
  text "PTH" at 6570.45,2682.91 h60
  text "Round" at 6814.77,2682.91 h60
  text "Top Layer - Bottom Layer" at 7175.11,2682.91 h60
  text "140 Total" at 5631.52,2583.29 h60
  text ".Layer_Name" at 577,-858.49 h60
M17 Embedded Cavity:
  text ".Layer_Name" at 577,-858.49 h60
M18 Embedded Assembly:
  text ".Layer_Name" at 577,-858.49 h60
M19 Embedded Keepout:
  text ".Layer_Name" at 577,-858.49 h60

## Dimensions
0,-400 to 1000,-400 on M2 Board Dimensions
0,0 to 0,3450 on M2 Board Dimensions
0,0 to 4950,0 on M2 Board Dimensions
